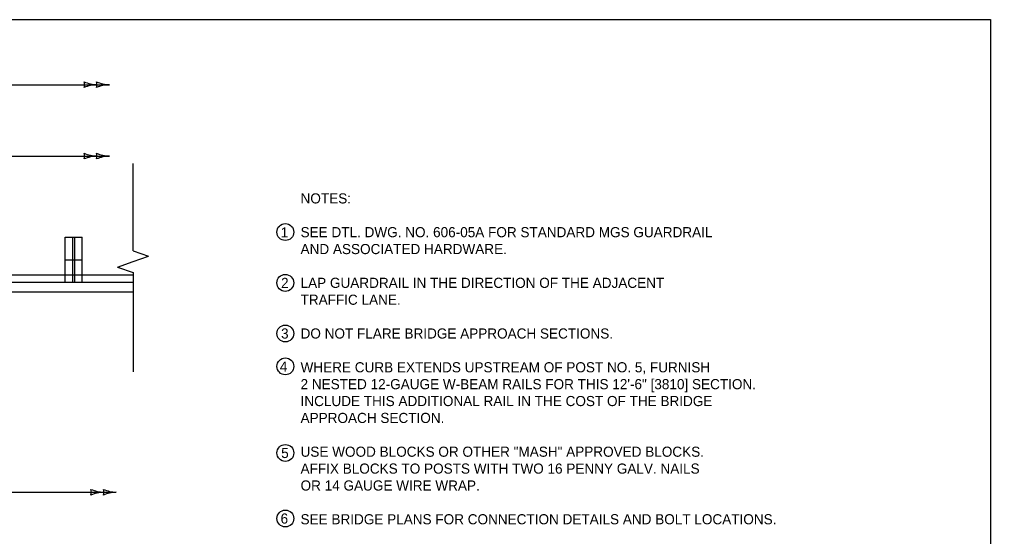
# Model space of a CAD drawing. Extents: x 49991 to 50160, y 49948 to 50051.
# Drawn here: x 50011 to 50016.75, y 49995.94 to 49999 of the extents above; entities that cross this region are included whole.
import ezdxf

# ---------------------------------------------------------------- set-up
doc = ezdxf.new("R2010")
doc.units = 0
for name, color, linetype in [('Level 1', 7, 'Continuous'), ('Level 2', 7, 'Continuous'), ('Level 3', 7, 'Continuous'), ('Level 4', 7, 'Continuous'), ('Level 6', 7, 'Continuous')]:
    doc.layers.add(name, color=color, linetype=linetype)

msp = doc.modelspace()

# ---------------------------------------------------------------- linework, layer by layer
at = {"layer": 'Level 1'}
for p, q in [((50011.2716, 49997.5761), (50011.2716, 49997.7094)), ((50011.2716, 49997.7094), (50011.3716, 49997.7094)), ((50011.3716, 49997.5761), (50011.3716, 49997.7094)), ((50011.2716, 49997.4428), (50011.2716, 49997.5761)), ((50011.2716, 49997.5761), (50011.3716, 49997.5761)), ((50011.2716, 49997.5761), (50011.3716, 49997.5761)), ((50011.3716, 49997.4428), (50011.3716, 49997.5761)), ((50010.1216, 49997.4868), (50011.2716, 49997.4867)), ((50011.3716, 49997.4867), (50011.6716, 49997.4867)), ((49999.8072, 49997.4432), (50011.6716, 49997.4427)), ((50011.2716, 49997.4428), (50011.3716, 49997.4428)), ((49999.8072, 49997.387), (50011.6716, 49997.3865))]:
    msp.add_line(p, q, dxfattribs=at)
msp.add_lwpolyline([(49999.3835, 49998.9992), (50016.7501, 49998.9992), (50016.7501, 49987.7988), (49999.3835, 49987.7988)], close=True, dxfattribs=at)
at = {"layer": 'Level 2'}
for centre in [(50012.5744, 49997.7401), (50012.5742, 49997.4389), (50012.5743, 49997.1394), (50012.5746, 49996.9448), (50012.5746, 49996.4319), (50012.5746, 49996.0437)]:
    msp.add_circle(centre, 0.05, dxfattribs=at)
at = {"layer": 'Level 3'}
for p, q in [((50008.1966, 49998.6127), (50011.5324, 49998.6127)), ((50006.3216, 49998.1899), (50011.5324, 49998.1899)), ((50008.1966, 49996.1994), (50011.5729, 49996.1994))]:
    msp.add_line(p, q, dxfattribs=at)
for centre, radius, start, end in [((50011.4681, 49998.8348), 0.2223, 247.45601, 267.63952), ((50011.3308, 49998.6127), 0.0548, 342.13882, 17.86118), ((50011.4705, 49998.38), 0.233, 92.82731, 112.07716), ((50011.5416, 49998.8348), 0.2223, 247.45601, 267.63952), ((50011.4042, 49998.6127), 0.0548, 342.13882, 17.86118), ((50011.5439, 49998.38), 0.233, 92.82731, 112.07716), ((50011.4681, 49998.412), 0.2223, 247.45601, 267.63952), ((50011.3308, 49998.1899), 0.0548, 342.13882, 17.86118), ((50011.4705, 49997.9572), 0.233, 92.82731, 112.07716), ((50011.5416, 49998.412), 0.2223, 247.45601, 267.63952), ((50011.4042, 49998.1899), 0.0548, 342.13882, 17.86118), ((50011.5439, 49997.9572), 0.233, 92.82731, 112.07716), ((50011.5086, 49996.4216), 0.2223, 247.45601, 267.63952), ((50011.3712, 49996.1994), 0.0548, 342.13882, 17.86118), ((50011.5109, 49995.9667), 0.233, 92.82731, 112.07716), ((50011.582, 49996.4216), 0.2223, 247.45601, 267.63952), ((50011.4447, 49996.1994), 0.0548, 342.13882, 17.86118), ((50011.5844, 49995.9667), 0.233, 92.82731, 112.07716)]:
    msp.add_arc(centre, radius, start, end, dxfattribs=at)
at = {"layer": 'Level 4'}
for p, q in [((50011.3154, 49997.5761), (50011.3154, 49997.7094)), ((50011.3279, 49997.5761), (50011.3279, 49997.7094)), ((50011.3154, 49997.4428), (50011.3154, 49997.5761)), ((50011.3279, 49997.4428), (50011.3279, 49997.5761)), ((50011.2716, 49997.4867), (50011.3716, 49997.4867))]:
    msp.add_line(p, q, dxfattribs=at)
at = {"layer": 'Level 6'}
for p, q in [((50011.6725, 49997.6297), (50011.6725, 49998.1459)), ((50011.6725, 49997.6297), (50011.7639, 49997.5973)), ((50011.5811, 49997.5325), (50011.6725, 49997.5649)), ((50011.6725, 49997.5649), (50011.7639, 49997.5973)), ((50011.5811, 49997.5325), (50011.6725, 49997.5001)), ((50011.6725, 49997.5001), (50011.6725, 49996.9118))]:
    msp.add_line(p, q, dxfattribs=at)

# ---------------------------------------------------------------- texts
at = {"layer": 'Level 2'}
for s, p in [('NOTES:', (50012.6646, 49997.9094)), ('1', (50012.5466, 49997.7079)), ('SEE DTL. DWG. NO. 606-05A FOR STANDARD MGS GUARDRAIL', (50012.6646, 49997.7094)), ('AND ASSOCIATED HARDWARE.', (50012.6646, 49997.6094)), ('2', (50012.5491, 49997.4089)), ('LAP GUARDRAIL IN THE DIRECTION OF THE ADJACENT', (50012.6646, 49997.4094)), ('TRAFFIC LANE.', (50012.6646, 49997.3094)), ('3', (50012.5491, 49997.1094)), ('DO NOT FLARE BRIDGE APPROACH SECTIONS.', (50012.6646, 49997.1094)), ('4', (50012.5417, 49996.9135)), ('WHERE CURB EXTENDS UPSTREAM OF POST NO. 5, FURNISH', (50012.6646, 49996.9094)), ('2 NESTED 12-GAUGE W-BEAM RAILS FOR THIS 12\'-6" [3810] SECTION.', (50012.6646, 49996.8094)), ('INCLUDE THIS ADDITIONAL RAIL IN THE COST OF THE BRIDGE', (50012.6646, 49996.7094)), ('APPROACH SECTION.', (50012.6646, 49996.6094)), ('5', (50012.5497, 49996.4019)), ('USE WOOD BLOCKS OR OTHER "MASH" APPROVED BLOCKS. ', (50012.6646, 49996.4094)), ('AFFIX BLOCKS TO POSTS WITH TWO 16 PENNY GALV. NAILS', (50012.6646, 49996.3094)), ('OR 14 GAUGE WIRE WRAP.', (50012.6646, 49996.2094)), ('6', (50012.5462, 49996.0137)), ('SEE BRIDGE PLANS FOR CONNECTION DETAILS AND BOLT LOCATIONS.', (50012.6646, 49996.0094))]:
    msp.add_text(s, height=0.06, dxfattribs=at).set_placement(p)

doc.saveas('drawing.dxf')
